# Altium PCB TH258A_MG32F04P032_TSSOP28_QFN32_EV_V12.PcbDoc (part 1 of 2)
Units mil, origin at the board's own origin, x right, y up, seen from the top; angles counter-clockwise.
Board outline 4094.49 x 2637.8 mil, 2 copper layers (Top Layer, Bottom Layer); 115 components, 96 nets, 518 pads, 260 vias.
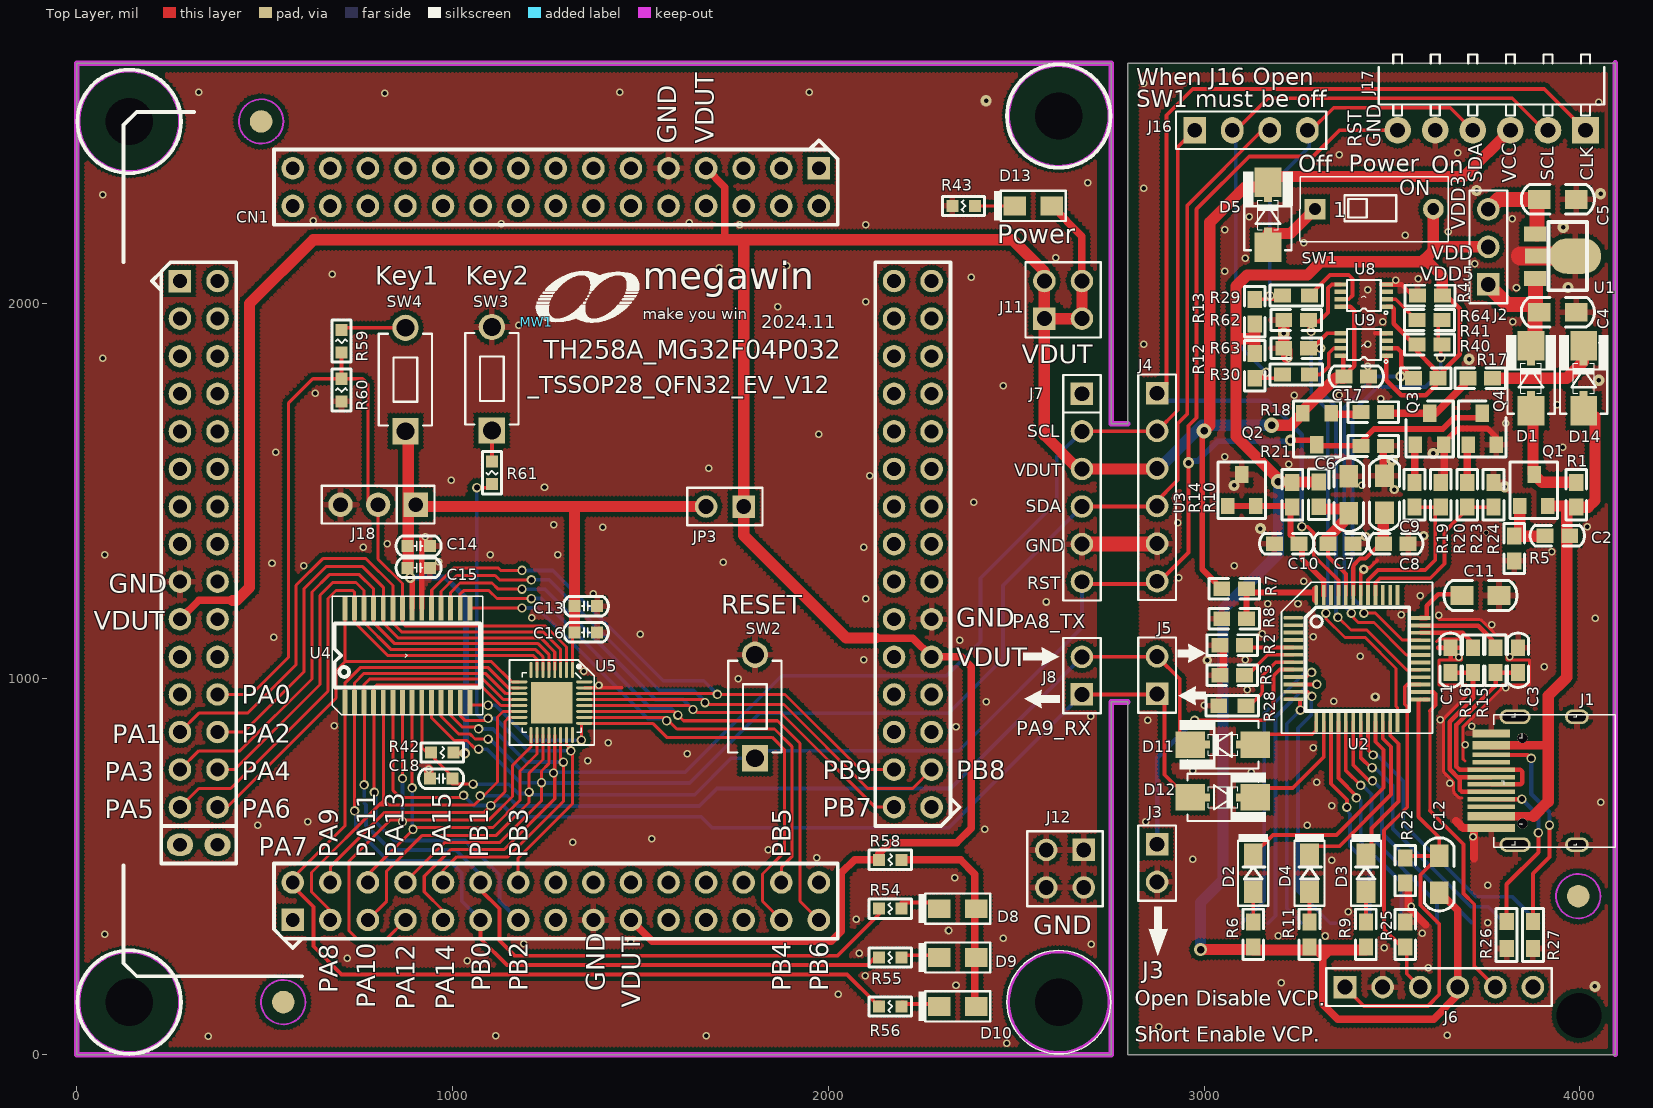
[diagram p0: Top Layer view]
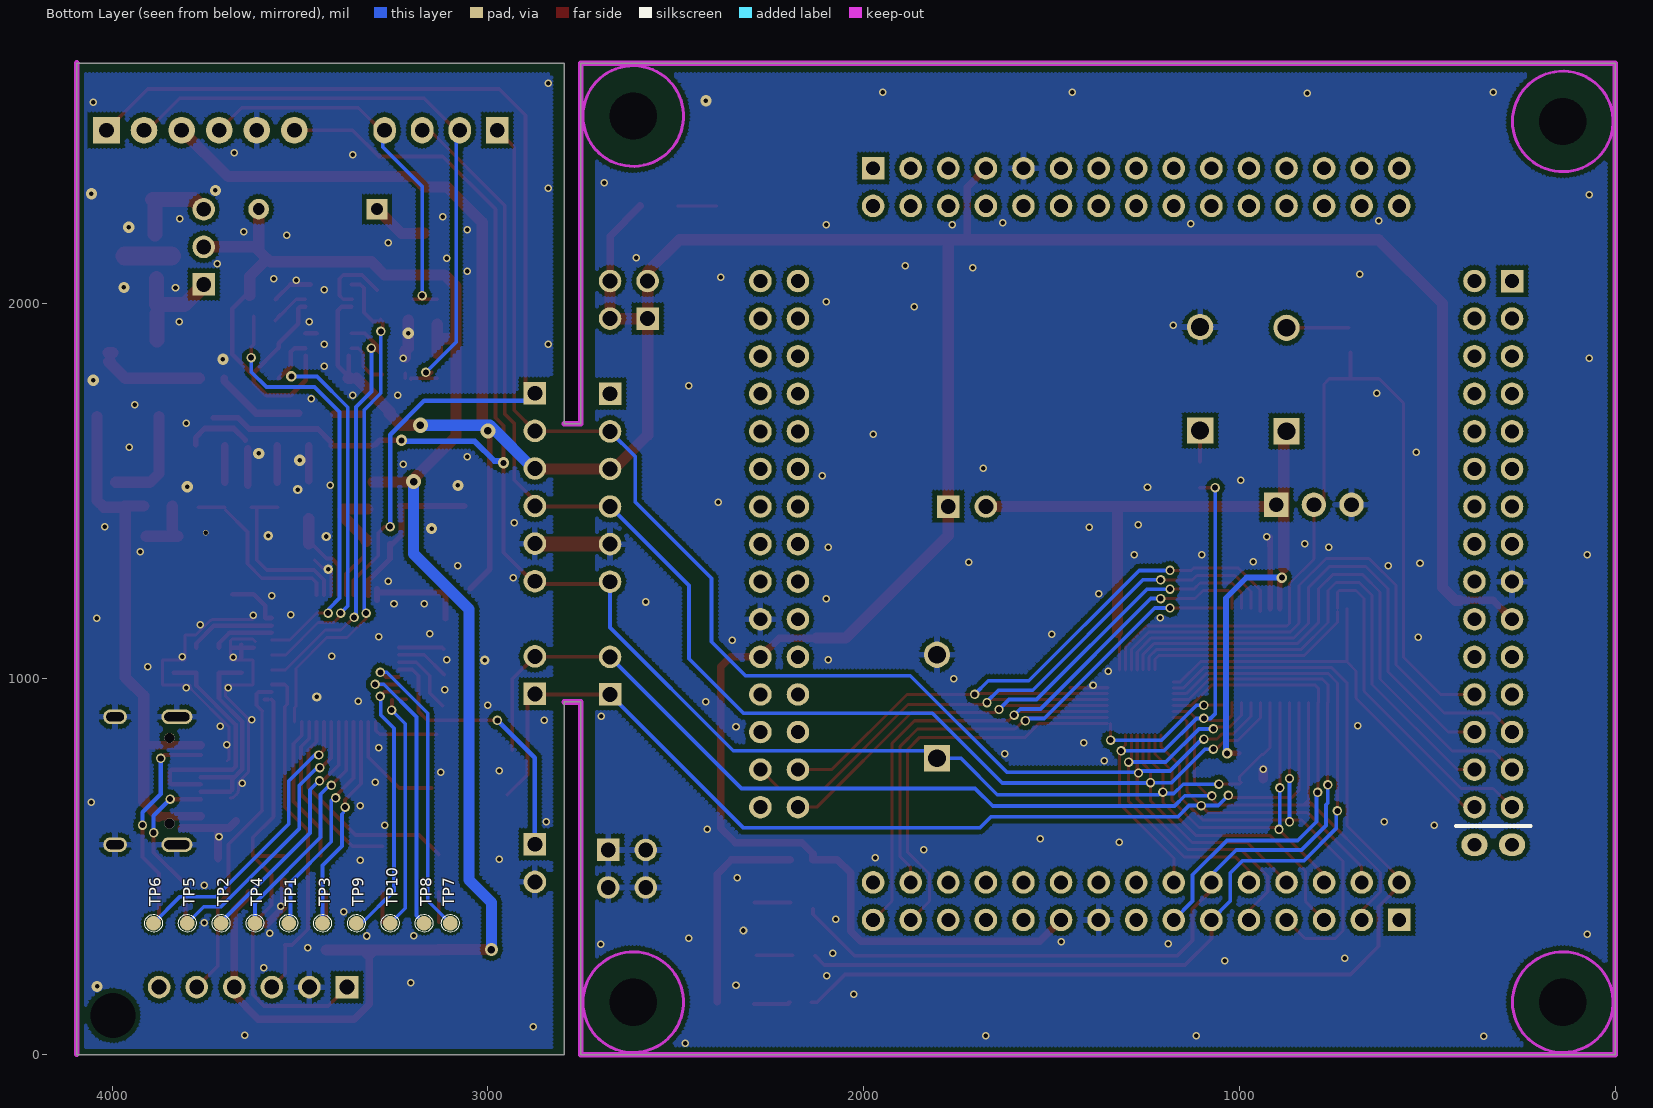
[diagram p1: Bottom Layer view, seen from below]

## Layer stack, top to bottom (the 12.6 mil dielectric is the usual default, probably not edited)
Top Layer: signal copper 1.4
Dielectric: dielectric 12.6, FR-4, Dk 4.8
Bottom Layer: signal copper 1.4

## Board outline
0,0 0,2637.8 2753.39,2637.8 2753.39,1678.74 2796.69,1678.74 2796.69,2637.8 4094.49,2637.8 4094.49,0 2796.69,0 2796.69,938.74 2753.39,938.74 2753.39,0

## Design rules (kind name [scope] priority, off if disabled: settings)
Clearance 12 [All] p1 off: gap=12
Clearance 7 [All] p2 off: gap=7
Clearance 6 [All] p3: gap=6
HoleSize 500-HoleSize [All] p1: absolutevalues=TRUE maxlimit=1500 minlimit=1 maxpercent=80.000 minpercent=20.000
PolygonConnect VIA [ISVIA] p1: connectstyle=Direct reliefconductorwidth=10 reliefentries=4 polygonreliefangle="90 Angle"
PolygonConnect "15 PolygonConnect" [All] p2: connectstyle=Relief reliefconductorwidth=15 reliefentries=4 polygonreliefangle="90 Angle"
RoomDefinition "3_MG32F04P032_QFN32 " [InComponentClass('3_MG32F04P032_QFN32 ')] p1: confinementstyle=ConfineIn formatcopy=TRUE lockcomponents=FALSE outline -14,-77 4129,-77 4129,2722 -14,2722
RoomDefinition 2_MG32F04P032_TSSOP28_V11 [InComponentClass('2_MG32F04P032_TSSOP28_V11')] p2: confinementstyle=ConfineIn formatcopy=TRUE lockcomponents=FALSE outline -39,-59 4148,-59 4148,2700 -39,2700
RoomDefinition 1_MLink_V14 [InComponentClass('1_MLink_V14')] p3: confinementstyle=ConfineIn formatcopy=TRUE lockcomponents=FALSE outline -63,-44 4163,-44 4163,2685 -63,2685
RoutingVias [All] p1: holewidth=16 width=25 viastyle="Through Hole" minholewidth=12 minwidth=25 maxholewidth=28 maxwidth=50
ShortCircuit [All] p1 off: allowed=FALSE
SilkscreenOverComponentPads [All] p1: minsilkscreentomaskgap=10
SolderMaskExpansion [All] p1: expansion=4
UnRoutedNet [All] p1 off:
Width [All] p1: maxlimit=100 minlimit=6 preferedwidth=8
24 further rules are at their usual default settings.

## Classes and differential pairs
component class 2_MG32F04P032_TSSOP28_V11: C14 C15 C18 CN1 D8 D9 D10 D13 J7 J8 J11 J12 J18 JP3 R42 R43 R54 R55 R56 R58 R59 R60 R61 SW2 SW3 SW4 U4
component class 1_MLink_V14: C1 C2 C3 C4 C5 C6 C7 C8 C9 C10 C11 C12 C17 D1 D2 D3 D4 D5 D11 D12 D14 J1 J2 J3 J4 J5 J6 J16 J17 MW1 Q1 Q2 Q3 Q4 R1 R2 R3 R4 R5 R6 R7 R8 R9 R10 R11 R12 R13 R14 R15 R16 R17 R18 R19 R20 R21 R22 R23 R24 R25 R26 R27 R28 R29 R30 R40 R41 R62 R63 R64 SW1 TP1 TP2 TP3 TP4 TP5 TP6 TP7 TP8 TP9 TP10 U1 U2 U3 U8 U9
component class "3_MG32F04P032_QFN32 ": C13 C16 U5

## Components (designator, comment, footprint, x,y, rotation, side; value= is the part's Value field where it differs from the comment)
C1 "15pF" 0603C 3655.59,1050 r270 top
C2 "0.1uF" 0603C 3940,1381.26 r0 top
C3 "15pF" 0603C 3835.59,1050 r270 top
C4 "4.7uF" 0805C 3941.38,1975.94 r0 top
C5 "4.7uF" 0805C 3941.38,2275.94 r0 top
C6 "4.7uF" 0805C 3385,1490 r90 top
C7 "0.1uF" 0603C 3363,1360 r0 top
C8 "0.1uF" 0603C 3510,1360 r0 top
C9 "4.7uF" 0805C 3480,1491.26 r90 top
C10 "0.1uF" 0603C 3220,1360 r0 top
C11 "4.7uF" 0805C 3735.59,1221.9 r0 top
C12 "4.7uF" 0805C 3625.59,480 r90 top
C13 "10uF" C-0603 1355.04,1193.74 r0 top
C14 "10uF" C-0603 910,1353.74 r180 top
C15 "0.1uF" C-0603 910,1295.74 r180 top
C16 "0.1uF" C-0603 1355.04,1123.74 r0 top
C17 "0.1uF" 0603C 3405,1805 r180 top
C18 "4.7uF" C-0603 970,735 r0 top
CN1 "QFP122-CKT" QFP122-P2.54-CKT 1275.04,1358.74 r0 top locked
D1 "1N5817" DIODE_SMA_SOD323 3870,1800 r90 top
D2 "Yellow" 0805D 3130.59,483.26 r90 top
D3 "Green" 0805D 3430.59,483.26 r90 top
D4 "Red" 0805D 3280.59,483.26 r90 top
D5 "1N5817" DIODE_SMA_SOD323 3170,2235 r90 top
D8 "Red" 0805D 2344.25,388.74 r180 top
D9 "Yellow" 0805D 2344.25,258.74 r180 top
D10 "Green" 0805D 2344.25,128.74 r180 top
D11 "1N5817" DIODE_SMA_SOD323 3050.04,825 r180 top
D12 "1N5817" DIODE_SMA_SOD323 3050.04,685 r0 top
D13 "Yellow" 0805D 2545.04,2258.74 r180 top
D14 "1N5817" DIODE_SMA_SOD323 4010,1800 r90 top
J1 "CJ-USB3-C16P" USB_CF_16_SMD 3799.28,729.12 r90 top
J2 "2&3 (0 ohm)" PS3P254#1 3756.42,2049.69 r90 top
J3 "VCP Option" PS2P254 2875.04,560 r270 top
J4 "OnBoard ICP/SWD Connector" PS6P254 2875.04,1760 r270 top
J5 "NC" PS2P254 2875.04,960 r90 top
J6 "CON6" PS6P254 3375.04,180 r0 top
J7 "CON6" PS6P254 2675.04,1758.74 r270 top locked
J8 "NC" PS2P254 2675.04,958.74 r90 top
J11 "CONN SOCKET 2x2/SM" PS2X2P254 2575.04,1958.74 r0 top
J12 "CONN SOCKET 2x2/SM" PS2X2P254 2680,545 r180 top
J16 "When J16 Open, SW1 must be off." PS4P254 2975.04,2460 r0 top
J17 "Off Board ICP/SWD Connector" PS6P254_90 4015.04,2460 r180 top locked
J18 "2&3 (0 ohm)" PS3P254#2 902.2,1463.74 r180 top
JP3 "JUMPER" PS2P254 1775.04,1458.74 r180 top
MW1 "MW-A4" MEGAWIN_3.4_1 1225.04,1948.74 r0 top
Q1 "IRLML6402" SOT23 3877.54,1501.97 r0 top
Q2 "2N3906" SOT23 3300.5,1665 r180 top
Q3 "3904" SOT23_132 3600.04,1665 r0 top
Q4 "3904" SOT23_132 3740.04,1665 r0 top
R1 "NC" 0603R#1 3990.04,1490 r270 top
R2 "NC" 0603R#1 3075.04,1090 r0 top
R3 "NC" 0603R#1 3075.04,1010 r0 top
R4 "3.3K" 0603R#1 3601,2020 r0 top
R5 "1M" 0603R#1 3825.04,1347 r270 top
R6 "1K" 0603R#1 3130.59,320.26 r270 top
R7 "30K" 0603R#1 3080,1240 r180 top
R8 "10K" 0603R#1 3080,1160 r0 top
R9 "1K" 0603R#1 3430.59,320.26 r270 top
R10 "10" 0603R#1 3305,1491.26 r90 top
R11 "1K" 0603R#1 3280.59,320.26 r270 top
R12 "1.5K" 0603R#1 3135,1833 r90 top
R13 "1.5K" 0603R#1 3135,1977 r270 top
R14 "1K" 0603R#1 3235,1490 r270 top
R15 "30" 0603R#1 3775.59,1050 r90 top
R16 "30" 0603R#1 3715.59,1050 r90 top
R17 "4.7K" 0603R#1 3735,1800 r0 top
R18 "1K" 0603R#1 3450.04,1710 r0 top
R19 "4.7K" 0603R#1 3560.04,1490 r270 top
R20 "10K" 0603R#1 3630.04,1490 r270 top
R21 "1M" 0603R#1 3450.04,1620 r180 top
R22 "47K" 0603R#1 3535.59,490 r270 top
R23 "4.7K" 0603R#1 3700.04,1490 r270 top
R24 "10K" 0603R#1 3770.04,1490 r270 top
R25 "47K" 0603R#1 3535.59,320 r270 top
R26 "5.1K" 0603R#2 3805.04,318.74 r270 top
R27 "5.1K" 0603R#2 3875.04,318.74 r90 top
R28 "0" 0603R#2 3075.04,928.74 r180 top
R29 "100" 0603R#2 3245,2020 r0 top
R30 "100" 0603R#2 3245,1810 r0 top
R40 "NC" 0603R#1 3590,1800 r180 top
R41 "1.5K" 0603R#1 3600,1890 r0 top
R42 "47K" R-0603 972.9,804.1 r180 top
R43 "1K" R-0603 2360.04,2258.74 r0 top
R54 "470" R-0603 2165.04,388.74 r0 top
R55 "470" R-0603 2165.04,258.74 r0 top
R56 "470" R-0603 2165.04,128.74 r0 top
R58 "0" R-0603 2165.04,518.74 r180 top
R59 "1K" R-0603 705.04,1898.74 r270 top
R60 "1M" R-0603 705.04,1768.74 r270 top
R61 "1K" R-0603 1105.04,1548.74 r90 top
R62 "47k" 0603R#3 3245,1955 r0 top
R63 "47k" 0603R#3 3245,1880 r0 top
R64 "100" 0603R#3 3600,1955 r180 top
SW1 "SW KEY-SPST" DIP2_SW 3295.04,2250 r0 top
SW2 "SW TACT-SPST" SW_T_2P 1805.04,926.54 r90 top
SW3 "Key2" SW_T_2P 1105.04,1798.74 r90 top
SW4 "Key1" SW_T_2P 875.04,1796.54 r90 top
TP1 "T POINT A" PIN1_1H0 3530.04,350 r90 bottom
TP2 "T POINT A" PIN1_1H0 3710.04,350 r90 bottom
TP3 "T POINT A" PIN1_1H0 3440.04,350 r180 bottom
TP4 "T POINT A" PIN1_1H0 3620.04,350 r180 bottom
TP5 "T POINT A" PIN1_1H0 3800.04,350 r180 bottom
TP6 "T POINT A" PIN1_1H0 3890.04,350 r180 bottom
TP7 "T POINT A" PIN1_1H0 3100.04,350 r180 bottom
TP8 "T POINT A" PIN1_1H0 3170.04,350 r180 bottom
TP9 "T POINT A" PIN1_1H0 3350.04,350 r180 bottom
TP10 "T POINT A" PIN1_1H0 3260.04,350 r90 bottom
U1 "AIC1734-33(SOT-89)" SOT89 3881.38,2125 r270 top
U2 "MG84FG516_LQFP48" LQFP48_7X7_050 3406.51,1054.39 r270 top locked
U3 "TL431A" SOT23 3100,1501.97 r0 top
U4 "MG32F04P032_TSSOP28_170P0.65" TSSOP28_170P065 880.04,1062.5 r0 top locked
U5 "MG32F04P032_QFN32_4X4P0.4" QFN32_4X4P040 1264.41,937.13 r270 top locked
U8 "SN74LVC2T45 (MSOP8_90P0.5)" MSOP8_90P0.5 3425,2020 r90 top
U9 "SN74LVC2T45 (MSOP8_90P0.5)" MSOP8_90P0.5 3425,1890 r90 top

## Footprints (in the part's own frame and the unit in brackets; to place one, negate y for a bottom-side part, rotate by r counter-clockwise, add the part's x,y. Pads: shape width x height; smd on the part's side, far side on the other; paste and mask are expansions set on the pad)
0603C [mil]
  rect 45x38 smd: 1(33,0) 2(-33,0)
  silkscreen extent -72,-28 72,28
0603R#1 [mil]
  rect 45x38 smd: 1(33,0) 2(-33,0)
  silkscreen extent -67,-28 67,28
0603R#2 [mil]
  rect 45x38 smd: 1(-36,0) 2(36,0)
  silkscreen extent -70,-28 70,28
0603R#3 [mil]
  rect 45x38 smd: 1(-33,0) 2(33,0)
  silkscreen extent -67,-28 67,28
0805C [mil]
  rect 60x50 smd: 1(-49.21,0) 2(49.21,0)
  silkscreen extent -97,-39 97,39
0805D [mil]
  rect 60x50 smd: 1(-49.21,0) 2(49.21,0)
  silkscreen extent -87,-40 104,40
C-0603 [mil]
  rect 32x32 smd: 1(-30,0) 2(30,0)
  silkscreen extent -60,-26 60,26
DIODE_SMA_SOD323 [mm]
  rect 2x1.8 smd: 1(-2.2,0) 2(2.2,0)
  rect 0.95x0.54 smd: 1(-1.35,0) 2(1.35,0)
  silkscreen extent -2.4,-1.68 2.92,1.68
DIP2_SW [mm]
  rect 1.4x1.4 hole 0.8: 1(0,0)
  round 1.4 hole 0.8: 2(8,0)
  silkscreen extent -1.02,-2.2 9.02,2.2
LQFP48_7X7_050 [mm]
  oval 0.254x1.35 smd: 1(-2.75,-4.292)
  rect 0.254x1.35 smd: 2(-2.25,-4.292) 3(-1.75,-4.292) 4(-1.25,-4.292) 5(-0.75,-4.292) 6(-0.25,-4.292) 7(0.25,-4.292) 8(0.75,-4.292) 9(1.25,-4.292) 10(1.75,-4.292) 11(2.25,-4.292) 12(2.75,-4.292) 25(2.763,4.292) 26(2.263,4.292) 27(1.763,4.292) 28(1.263,4.292) 29(0.763,4.292) 30(0.263,4.292) 31(-0.237,4.292) 32(-0.737,4.292) 33(-1.237,4.292) 34(-1.737,4.292) 35(-2.237,4.292) 36(-2.737,4.292)
  rect 1.35x0.254 smd: 13(4.286,-2.744) 14(4.286,-2.244) 15(4.286,-1.744) 16(4.286,-1.244) 17(4.286,-0.744) 18(4.286,-0.244) 19(4.286,0.256) 20(4.286,0.756) 21(4.286,1.256) 22(4.286,1.756) 23(4.286,2.256) 24(4.286,2.756) 37(-4.286,2.756) 38(-4.286,2.256) 39(-4.286,1.756) 40(-4.286,1.256) 41(-4.286,0.756) 42(-4.286,0.256) 43(-4.286,-0.244) 44(-4.286,-0.744) 45(-4.286,-1.244) 46(-4.286,-1.744) 47(-4.286,-2.244)
  oval 1.35x0.254 smd: 48(-4.286,-2.744)
  silkscreen extent -5.15,-5.09 5.05,5.11
MEGAWIN_3.4_1 [mil]
  silkscreen extent -2,0 272,135
MSOP8_90P0.5 [mm]
  rect 0.3x0.85 smd: 1(-0.75,-1.55) 2(-0.25,-1.55) 3(0.25,-1.55) 4(0.75,-1.55) 5(0.75,1.55) 6(0.25,1.55) 7(-0.25,1.55) 8(-0.75,1.55)
  silkscreen extent -1.26,-1.61 1.05,1.14
PIN1_1H0 [mm]
  round 1 smd: 1(0,0)
  silkscreen extent -0.6,-0.6 0.6,0.6
PS2P254 [mil]
  rect 60x60 hole 39.37: 1(0,0)
  round 60 hole 39.37: 2(100,0)
  silkscreen extent -50,-50 150,50
PS2X2P254 [mil]
  rect 60x60 hole 39.37: 1(0,0)
  round 60 hole 39.37: 2(0,100) 3(100,0) 4(100,100)
  silkscreen extent -50,-50 150,150
PS3P254#1 [mil]
  rect 60x60 hole 39.37: 1(0,0)
  round 60 hole 39.37: 2(100,0) 3(200,0)
  silkscreen extent -50,-50 250,50
PS3P254#2 [mil]
  rect 65x65 hole 39.37: 1(0,0)
  round 65 hole 39.37: 2(100,0) 3(200,0)
  silkscreen extent -50,-50 250,50
PS4P254 [mil]
  rect 60x70 hole 39.37: 1(0,0)
  oval 60x70 hole 39.37: 2(100,0) 3(200,0) 4(300,0)
  silkscreen extent -50,-50 350,50
PS6P254 [mil]
  rect 60x60 hole 39.37: 1(0,0)
  round 60 hole 39.37: 2(100,0) 3(200,0) 4(300,0) 5(400,0) 6(500,0)
  silkscreen extent -50,-50 550,50
PS6P254_90 [mm]
  rect 1.8x1.8 hole 1: 1(0,0)
  round 1.8 hole 1: 2(2.54,0) 3(5.08,0) 4(7.62,0) 5(10.16,0) 6(12.7,0)
  silkscreen extent -1.27,-5.11 13.97,-1
QFN32_4X4P040 [mm]
  oval 1.1x0.2 smd: 1(-2.2,1.4) 2(-2.2,1) 3(-2.2,0.6) 4(-2.2,0.2) 5(-2.2,-0.2) 6(-2.2,-0.6) 7(-2.2,-1) 8(-2.2,-1.4) 17(2.2,-1.4) 18(2.2,-1) 19(2.2,-0.6) 20(2.2,-0.2) 21(2.2,0.2) 22(2.2,0.6) 23(2.2,1) 24(2.2,1.4)
  oval 0.2x1.1 smd: 9(-1.4,-2.2) 10(-1,-2.2) 11(-0.6,-2.2) 12(-0.2,-2.2) 13(0.2,-2.2) 14(0.6,-2.2) 15(1,-2.2) 16(1.4,-2.2) 25(1.4,2.2) 26(1,2.2) 27(0.6,2.2) 28(0.2,2.2) 29(-0.2,2.2) 30(-0.6,2.2) 31(-1,2.2) 32(-1.4,2.2)
  rect 2.8x2.8 smd: 33(0,0)
  silkscreen extent -2.87,-2.87 2.87,2.87
QFP122-P2.54-CKT [mil]
  rect 60x60 hole 37: 1(-700,-1000) 61(700,1000) 91(-1000,700)
  round 60 hole 37: 2(-700,-900) 3(-600,-1000) 4(-600,-900) 5(-500,-1000) 6(-500,-900) 7(-400,-1000) 8(-400,-900) 9(-300,-1000) 10(-300,-900) 11(-200,-1000) 12(-200,-900) 13(-100,-1000) 14(-100,-900) 15(0,-1000) 16(0,-900) 17(100,-1000) 18(100,-900) 19(200,-1000) 20(200,-900) 21(300,-1000) 22(300,-900) 23(400,-1000) 24(400,-900) 25(500,-1000) 26(500,-900) 27(600,-1000) 28(600,-900) 29(700,-1000) 30(700,-900) 31(1000,-700) 32(900,-700) 33(1000,-600) 34(900,-600) 35(1000,-500) 36(900,-500) 37(1000,-400) 38(900,-400) 39(1000,-300) 40(900,-300) 41(1000,-200) 42(900,-200) 43(1000,-100) 44(900,-100) 45(1000,0) 46(900,0) 47(1000,100) 48(900,100) 49(1000,200) 50(900,200) 51(1000,300) 52(900,300) 53(1000,400) 54(900,400) 55(1000,500) 56(900,500) 57(1000,600) 58(900,600) 59(1000,700) 60(900,700) 62(700,900) 63(600,1000) 64(600,900) 65(500,1000) 66(500,900) 67(400,1000) 68(400,900) 69(300,1000) 70(300,900) 71(200,1000) 72(200,900) 73(100,1000) 74(100,900) 75(0,1000) 76(0,900) 77(-100,1000) 78(-100,900) 79(-200,1000) 80(-200,900) 81(-300,1000) 82(-300,900) 83(-400,1000) 84(-400,900) 85(-500,1000) 86(-500,900) 87(-600,1000) 88(-600,900) 89(-700,1000) 90(-700,900) 92(-900,700) 93(-1000,600) 94(-900,600) 95(-1000,500) 96(-900,500) 97(-1000,400) 98(-900,400) 99(-1000,300) 100(-900,300) 101(-1000,200) 102(-900,200) 103(-1000,100) 104(-900,100) 105(-1000,0) 106(-900,0) 107(-1000,-100) 108(-900,-100) 109(-1000,-200) 110(-900,-200) 111(-1000,-300) 112(-900,-300) 113(-1000,-400) 114(-900,-400) 115(-1000,-500) 116(-900,-500) 117(-1000,-600) 118(-900,-600) 119(-1000,-700) 120(-900,-700)
  oval 70x60 hole 37: 121(-1000,-800) 122(-900,-800)
  silkscreen extent -1150,-1150 1075,1150
R-0603 [mil]
  rect 32x32 smd: 1(-30,0) 2(30,0)
  silkscreen extent -56,-26 56,26
SOT23 [mil]
  rect 36x43.31 smd: 1(-37.5,-41.97) 2(37.5,-41.97)
  rect 36x46.06 smd: 3(0.5,41.97)
  silkscreen extent -63,-74 63,75
SOT23_132 [mil]
  rect 36x43.31 smd: 1(-37.5,-41.97) 3(37.5,-41.97)
  rect 36x46.06 smd: 2(0.5,41.97)
  silkscreen extent -63,-74 63,75
SOT89 [mm]
  rect 1.016x1.5 smd: 1(-1.5,0) 3(1.5,0)
  oval 2.4x3.5 smd: 2(0,2.7)
  rect 1.016x2.6 smd: 2(0,0.6)
  silkscreen extent -2.3,0.9 2.3,3.5
SW_T_2P [mil]
  rect 70x70 hole 47.24: 1(-137.79,0)
  round 70 hole 47.24: 2(137.79,0)
  silkscreen extent -122,-71 122,71
TSSOP28_170P065 [mil]
  rect 13x65 smd: 1(-166.34,-125) 2(-140.75,-125) 3(-115.16,-125) 4(-89.57,-125) 5(-63.98,-125) 6(-38.39,-125) 7(-12.8,-125) 8(12.8,-125) 9(38.39,-125) 10(63.98,-125) 11(89.57,-125) 12(115.16,-125) 13(140.75,-125) 14(166.34,-125) 15(166.34,125) 16(140.75,125) 17(115.16,125) 18(89.57,125) 19(63.98,125) 20(38.39,125) 21(12.8,125) 22(-12.8,125) 23(-38.39,125) 24(-63.98,125) 25(-89.57,125) 26(-115.16,125) 27(-140.75,125) 28(-166.34,125)
  silkscreen extent -200,-158 201,158
USB_CF_16_SMD [mm]
  rect 0.55x3.2 smd: A1(-3.2,0.9) A4(-2.4,0.9)
  rect 0.3x3.2 smd: A5(-1.25,0.9) A6(-0.25,0.9) A7(0.25,0.9) B6(0.75,0.9) B7(-0.75,0.9) B8(-1.75,0.9)
  rect 0.3x2.54 smd: A8(1.25,0.9) B5(1.75,0.9)
  rect 0.55x2.54 smd: A9(2.4,0.9) A12(3.2,0.9)
  oval 1x2.1 hole 0.6 slot 1.7 at 90 deg: M1(-4.32,-0.718) M2(4.32,-0.718)
  oval 1x1.6 hole 0.6 slot 1.2 at 90 deg: M3(4.32,-4.898) M4(-4.32,-4.898)
  round 0.7 hole 0.7 unplated: M5(-2.89,-1.218) M6(2.89,-1.218)
  silkscreen extent -4.48,-7.5 4.55,0.74

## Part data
C1 C3 C7 C12 C13 C14 C15 C16 C18: library part "CAP NP_Dup1"
C2 C8 C10 C17: library part "CAP NP"
C4 C5: library part "C NP"
C6 C9 C11: library part CAP
D1 D5 D11 D12 D14: library part "DIODE SCHOTTKY"
D2 D3 D4: library part Led0_0
D8 D9 D10 D13: library part LED
J1: "TPYE-C-9"
J2 J18: library part CON3
J3 J5 J8: library part CON2
J4 J17: library part CON6
J7: library part CON6_Dup1
J16: library part CON4
MW1: library part MW_A4_2
Q1: library part "MOSFET P GSD"
Q2: library part 2N3906_0
Q3 Q4: library part "NPN BCE"
R1 R2 R3 R4 R28 R43 R54 R55 R56 R58: library part R_Dup4
R5 R6 R7 R8 R9 R11 R12 R13 R17 R18 R19 R22 R23 R25 R26 R27 R29 R30: library part R_Dup2
R10 R14 R15 R16: library part R_Dup5
R20 R21 R24: library part R_Dup1
R40 R41 R42 R59 R60 R61 R62 R63: library part R_Dup3
R64: library part R
SW3 SW4: library part "SW TACT-SPST"
U1: library part AIC1722-33
U3: library part TL431/CYL
U4: library part MDF101A/TSSOP28
U5: library part MG32F005_QFN32
U8 U9: library part SN74LVC2T45

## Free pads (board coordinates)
  round 120 hole 125.98 unplated: 0(140,140) 0(140,2483.43) 0(2613.39,140) 0(2613.39,2497.8)
  round 60 smd mask+39.37: 0(491,2483.43) 0(550,140) 0(3995.59,421.9)
  round 100 hole 120 unplated: 0(3997.8,104.65)

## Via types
v1: diameter 20, hole 12, Top Layer to Bottom Layer, tented both sides, 172 vias
v2: diameter 25, hole 16, Top Layer to Bottom Layer, tented both sides, 58 vias
v3: diameter 30, hole 12, Top Layer to Bottom Layer, tented both sides, 14 vias
v4: diameter 25, hole 12, Top Layer to Bottom Layer, tented both sides, 6 vias
v5: diameter 40, hole 20, Top Layer to Bottom Layer, tented both sides, 3 vias
v6: diameter 28, hole 16, Top Layer to Bottom Layer, tented both sides, 3 vias
v7: diameter 30, hole 16, Top Layer to Bottom Layer, tented both sides, 2 vias
v8: diameter 15, hole 12, Top Layer to Bottom Layer, tented both sides, 1 vias
v9: diameter 35, hole 20, Top Layer to Bottom Layer, tented both sides, 1 vias

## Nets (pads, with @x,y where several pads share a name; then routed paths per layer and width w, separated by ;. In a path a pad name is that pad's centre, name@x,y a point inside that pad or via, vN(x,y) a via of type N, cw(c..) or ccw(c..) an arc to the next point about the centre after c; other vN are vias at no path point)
2.495V: C10.1 R14.1 U2.47 U3.1 U3.2 | length 442.3
  Top Layer w15: U3.1@3062.5,1460 U3.2@3137.5,1460 R14.1@3235,1460 ; R14.1@3230,1452 3230,1383 C10.1@3253,1360 3260.59,1360 3260.59,1319.45 3318.18,1261.86 U2.47@3318.18,1223.13
516P24: TP7.1 U2.9 | length 807.9
  Top Layer w10: U2.9@3237.52,1005.18 3271.48,1005.18 v2@3285.04,1018.74
  Bottom Layer w10: TP7.1@3100.04,350 3160.04,410 3160.04,908.74 3269.04,1017.74 v2(3286.04,1017.74)
516P25: TP8.1 U2.10 | length 765.6
  Top Layer w10: U2.10@3237.52,985.49 v2@3300.04,985.49
  Bottom Layer w10: TP8.1@3170.04,350 3190.04,370 3190.04,898.74 3277.04,985.74 v2(3300.04,985.74)
516P26: TP9.1 U2.11 | length 719.6
  Top Layer w10: U2.11@3237.52,965.81 3275.04,965.81 v2@3285.04,955.81
  Bottom Layer w10: v2@3285.04,953.74 3285.04,903.74 3250.04,868.74 3250.04,435.95 3335.99,350 TP9.1@3350.04,350
  other v2: 3287.04,953.74
516P27: TP10.1 U2.12 | length 651.8
  Top Layer w10: U2.12@3217.15,946.12 U2.12@3237.52,946.12 ; v2@3255.04,911.51 3255.04,916.74 U2.12@3255.04,944.74
  Bottom Layer w10: v2(3256.04,916.74) 3220.04,880.74 3220.04,390 TP10.1@3260.04,350
516P32: TP3.1 U2.15 | length 550.9
  Top Layer w10: U2.15@3337.86,885.65 3337.86,720.92 3380.04,678.74 v2@3380.04,668.74
  Bottom Layer w10: 3385.04,643.74 3388.62,640.16 3388.62,555.16 3440.04,503.74 TP3.1@3440.04,350
  other v2: 3380.04,658.74
516P33: TP1.1 U2.16 | length 664
  Top Layer w10: U2.16@3357.55,885.65 3357.55,736.23 v2@3407.54,686.24 ; v2@3409.54,688.24 v2@3412.04,685.74
  Bottom Layer w10: v2@3405.04,688.74 3407.54,686.24 3416.9,676.88 3416.9,566.88 ; 3416.9,618.74 3416.9,566.88 ; TP1.1@3525.04,350 3525.04,458.74 3416.9,566.88
  other v2: 3405.04,683.74
516P34: TP4.1 U2.17 | length 635.3
  Top Layer w10: U2.17@3377.23,885.65 3377.23,756.55 v2(3416.72,717.06)
  Bottom Layer w10: v2@3420.64,717.8 3445.19,693.26 3445.19,578.59 3620.04,403.74 TP4.1@3620.04,350
516P35: TP2.1 U2.18 | length 668.2
  Top Layer w10: U2.18@3396.92,885.65 3396.92,770.86 3443.54,724.24 v2@3445.04,722.74
  Bottom Layer w10: v2@3450.04,728.74 3473.47,705.31 3473.47,590.31 TP2.1@3711.91,351.87
  other v2: 3448.04,728.74
516P36: TP5.1 U2.19 | length 736.6
  Top Layer w10: U2.19@3416.6,885.65 3416.6,791.18 v2@3445.54,762.24
  Bottom Layer w10: v2(3447.04,763.74) 3455.04,763.74 3501.76,717.02 3501.76,602.02 3710.04,393.74 3756.3,393.74 TP5.1@3800.04,350 TP5.1@3790.59,350
516P37: TP6.1 U2.20 | length 795.9
  Top Layer w10: U2.20@3436.29,885.65 3436.29,811.49 v2(3450.04,797.74)
  Bottom Layer w10: v2(3450.04,797.74) 3461.04,797.74 3530.04,728.74 3530.04,613.74 3723.04,420.74 3819.3,420.74 TP6.1@3890.04,350 TP6.1@3880.59,350
CHIP_VDD: C13.1 C14.2 C15.2 C16.1 J18.1 JP3.2 R42.1 SW4.1 U4.21 U5.1 | length 2309.8
  Top Layer w9: U5.1@1319.53,1023.74 C16.1@1319.53,1123.74
  Top Layer w15: U4.21@892.83,1187.5 v6@892.83,1269.74 ; R42.1@1003,802 v6@1028.59,802
  Top Layer w30: C15.2@882.2,1295.74 C14.2@882.2,1353.74 ; C14.2@882.2,1365.74 C14.2@882.2,1353.74 ; SW4.1@882.2,1658.74 882.2,1463.74 J18.1@882.2,1443.74 ; SW4.1@888,1658.74 SW4.1@888,1660 ; J18.1@902.2,1463.74 J18.1@897.2,1458.74 ; C16.1@1325.04,1123.74 C13.1@1325.04,1193.74 1325.04,1458.74 ; JP3.2@1675.04,1458.74 1325.04,1458.74 ; C14.2@882.2,1353.74 J18.1@882.2,1443.74 ; J18.1@882.2,1443.74 J18.1@897.2,1458.74 ; J18.1@897.2,1458.74 902.2,1458.74 1325.04,1458.74
  Bottom Layer w15: v6(887.2,1269.74) 981.42,1269.74 1036,1215.16 v6@1036,802
  other v6: 1033,802
D+: C3.1 J1.A6 J1.B6 R15.2 | length 648.6
  Top Layer w12: J1.A6@3763.84,719.27 3842.37,719.27 3847.09,724 3847.09,753 3841.45,758.64 J1.B6@3763.84,758.64 3679.95,758.64 3671.59,767 3671.59,878.54 3775.59,982.54 R15.2@3775.59,1017 C3.1@3835.59,1017
D-: C1.1 J1.A7 J1.B7 R16.2 | length 590.1
  Top Layer w12: C1.1@3655.59,1017 R16.2@3715.59,1017 3715.59,948 3653.59,886 3653.59,759.54 3679.75,733.39 ; 3675.59,738.96 3685.99,738.96 ; 3680.59,734.23 3680.59,705.23 3686.23,699.59 J1.B7@3763.84,699.59 ; 3680.94,733.9 3685.99,738.96 ; J1.A7@3763.84,738.96 3685.99,738.96
DET_VDUT: R7.2 R8.1 U2.48 | length 292.1
  Top Layer w15: R8.1@3113,1160 R7.2@3113,1240 3123,1230 3290.98,1230 ; U2.48@3295.04,1210 3295.04,1223.13 U2.48@3295.04,1240
DUT_CLK: J4.1 J17.1 U2.45 | length 2846.5
  Top Layer w10: J4.1@2875.04,1760 2900.04,1785 2900.04,2500.04 2970,2570 3905.04,2570 J17.1@4015.04,2460 ; v2(3260,1405) 3275,1405 3292,1388 3292,1327.92 3357.55,1262.37 U2.45@3357.55,1223.13
  Bottom Layer w12: J4.1@2875.04,1760 2880.04,1760 2900.04,1740 3170,1740 3260,1650 v2(3260,1405)
DUT_RST: C18.2 CN1.5 J4.6 J7.6 J17.6 Q2.3 Q4.2 R21.1 R42.2 SW2.1 U4.9 U5.19 | length 5742.6
  Top Layer w8: CN1.5@775.04,358.74 825.04,408.74 825.04,488.74 920.04,583.74 1116.74,583.74 1204.04,671.04 v2(1204.04,698.74) 1204.04,749.04 1240.79,785.79 U5.19@1240.79,850.51 ; U4.9@918.43,937.5 918.43,817.57 937.4,798.6 941.4,798.6 1000,740 C18.2@1000,735 C18.2@1000,730 ; C18.2@995,725 1000,720 v2(1055,720)
  Top Layer w10: J7.6@2676.04,1252.74 2875.04,1252.74 2878.67,1256.37 2958.79,1336.49 v7(2958.79,1575) 2958.79,1673.79 2980.04,1695.04 2980.04,2250.04 3120,2390 3290,2390 3360,2460 J17.6@3515.04,2460
  Top Layer w15: v7(3230,1635) 3288.03,1635 Q2.3@3300,1623.03 ; Q2.3@3308.03,1620 R21.1@3417.04,1620 3417.04,1629.56 3452.48,1665 3635,1665 3665,1695 Q4.2@3730.63,1695
  Bottom Layer w10: v2(1055,720) 1150,720 1175,695 1198.3,695 1203.04,699.74 v2@1204.04,700.74 ; 1214.78,692 1644.57,692 1741.31,788.74 SW2.1@1805.04,788.74 ; SW2.1@1790.04,788.74 SW2.1@1805.04,788.74 ; J7.6@2675.04,1258.74 2675.04,1136.74 2347.04,808.74 1825.04,808.74 SW2.1@1805.04,788.74
  Bottom Layer w15: v7(2958.79,1575) 2958.79,1580 2983,1580 3035,1632 v7@3230,1632
DUT_SCL: J16.2 J17.2 R12.2 R30.1 | length 1704.6
  Top Layer w10: J16.2@3075.04,2460 3085,2460 3170,2545 3820,2545 J17.2@3905,2460 ; R12.2@3135,1800 3165,1800 R30.1@3203.31,1800 ; R12.2@3150,1816 3150.5,1815.5 3157.5,1808.5 3165,1801 ; R30.1@3205,1798.31 R30.1@3205,1800 ; R30.1@3220,1800 3220,1810 R30.1@3220,1812.69 ; J17.2@3890,2460 J17.2@3905,2460 ; J17.2@3910.02,2465.02 J17.2@3915.04,2460 J17.2@3905,2460
  Bottom Layer w10: J16.2@3084.3,2450.74 3084.3,1896.7 v2(3165,1816)
DUT_SDA: J16.4 J17.4 R13.2 R29.1 | length 1034.3
  Top Layer w10: R13.2@3135,2010 3175,2010 R29.1@3199,2010 ; J16.4@3280.02,2455.02 3345,2520 3655.04,2520 J17.4@3715.04,2460
  Bottom Layer w10: v2@3175,2015 v2(3175,2020) 3175,2310 3280.02,2415.02 J16.4@3280.02,2455.02
FAIL: D4.2 U2.22 | length 476
  Top Layer w10: D4.2@3280.59,555 3360.14,555 3497.35,692.22 3497.35,819.59 3475.66,841.28 U2.22@3475.66,885.65
GND_POWER: C1.2 C3.2 C4.2 C5.2 C6.2 C7.1 C8.1 C9.2 C10.2 C11.2 C13.2 C14.1 C15.1 C16.2 C17.2 C18.1 CN1.17 CN1.41 CN1.69 CN1.107 J1.A1 J1.A12 J1.M1 J1.M2 J1.M3 J1.M4 J3.2 J4.5 J6.2 J7.5 J12.1 J12.2 J12.3 J12.4 J17.5 J18.3 Q3.3 Q4.3 R2.2 R3.2 R4.2 R5.1 R8.2 R20.2 R21.2 R22.1 R24.2 R25.2 R26.2 R27.1 R28.2 R43.1 R60.2 R62.1 R63.1 SW2.2 SW3.2 U1.2 U2.42 U3.3 U4.20 U5.31 U8.4 U9.4 | length 3377.1
  Top Layer w8: 3619.08,1099.79 3625.08,1105.79 3655.59,1105.79 3680.76,1105.79 3685.59,1100.96 3685.59,1058 3685.59,1050.5 3677.59,1050.5 3625.59,1050.5 3625.59,983.5 3690.59,983.5 3698.59,983.5 3698.59,977 3698.59,955.04 3641.57,898.02 ; v1@3619.59,1164 3625.12,1158.47 3729.12,1158.47 ; 3641.57,747.52 cw(c3653.59,759.54) 3636.59,759.54 ; 3641.59,898 ccw(c3653.61,885.98) 3636.61,885.98 3636.59,759.54 ; 3674.21,687.57 ccw(c3686.23,699.59) 3686.23,682.59 cw(c3686.23,699.59) 3674.19,687.59 3668.59,693.19 ; 3694.59,781.64 3688.59,787.64 3688.59,825 3688.59,871.5 3787.59,970.5 ccw(c3775.59,982.54) 3792.59,982.54 cw(c3775.59,982.54) 3787.61,970.52 ; 3792.59,983.5 3802.59,983.5 3865.59,983.5 3865.59,1050.5 3813.59,1050.5 3805.59,1050.5 3805.59,1059 3805.59,1116.5 3778.13,1116.5 3758.11,1136.52 3741.16,1153.47 ; 3636.59,759.54 ccw(c3653.59,759.54) 3641.59,747.5 3660.34,728.75 3663.59,725.5 3663.59,722 3663.59,705.23 ; 3663.59,705.23 ccw(c3680.59,705.23) 3668.59,693.19 ; 3663.59,705.23 ccw(c3680.59,705.23) 3668.57,693.21 ; 3729.12,1158.47 cw(c3729.12,1141.47) 3741.16,1153.47 ; 3729.12,1158.47 cw(c3729.12,1141.47) 3741.14,1153.49
  Top Layer w9: U5.31@1351.02,976.5 1390,976.5 1451.02,976.5
  Top Layer w10: U2.42@3416.6,1223.13 3416.6,1283.6 v4(3425,1292) 3429,1296 3441,1296 3461,1316
  Top Layer w12: 3455,1919.53 U9.4@3486.02,1919.53 ; U8.4@3471.02,2049.53 U8.4@3486.02,2049.53 3510,2049.53 3525.47,2049.53 3561.5,2013.5 R4.2@3565,2010 ; 3623.59,1083 C1.2@3655.59,1083 C1.2@3656.59,1083 ; 3656.59,1054 C1.2@3656.59,1083 ; C1.2@3656.59,1091 C1.2@3656.59,1083 ; 3683.59,1083 C1.2@3656.59,1083
  Top Layer w15: U4.20@918.43,1187.5 918.43,1295.74 918.43,1353.74 v1@918.43,1378.44 ; 920,1353.74 v1@920,1378.44 ; Q3.3@3645.29,1635.29 3676.24,1666.24 3753.7,1666.24 3777.54,1642.4 Q4.3@3777.54,1623.03
  Top Layer w20: R3.2@3051.04,1010 3051.04,1090 R2.2@3051.04,1090.09 ; C9.2@3477.04,1528 3477.04,1540.47 3477.04,1582 R21.2@3477.04,1620 ; R22.1@3543.59,461 3543.59,457 3543.59,395.74 3543.59,391.89 3545.39,390.09 3559.03,376.44 3590.08,345.4 ; R20.2@3639.04,1515 3639.04,1523 Q3.3@3639.04,1612.53
  Top Layer w22: 3670.59,621.9 3689.38,603.12 J1.A1@3763.84,603.12 J1.A1@3815.59,603.12 ; 3718.47,522.79 3718.47,580 J1.A1@3718.47,597.25
  Top Layer w25: C18.1@937,734 937,735 v1(937,760)
  Top Layer w30: R63.1@3212,1880 v3(3212,1920) R62.1@3212,1955 ; v1@3220,1855 R63.1@3220,1875
  Top Layer w40: J7.5@2675.04,1358.74 J4.5@2875.04,1358.74
  Top Layer w50: 3841.82,2125 U1.2@3905,2125 U1.2@3966.38,2125
  other v1: 2475.04,30.64 349.94,48.74 1115.04,50.64 1675.04,50.64 3647.59,51.9 2879.94,75 2026.04,160.64 2339.94,185 3205.59,191.9 2098.04,210.64 3596.59,231.9 1039.94,250.74 719.94,256.74 2083.04,270.64 3479.94,285 2699.94,293.74 1189.94,295 1475,300.64 2466,310.64 3322.59,316 3197.59,317 75.04,320.64 3579.94,323.74 2320,330.64 3755,350.64 2074.04,360.64 3384.04,380.64 3551.04,395.74 3755,450.64 2336.04,470.64 3339.94,518 2969.94,520 1969.94,524.74 1839.94,545.74 1319.94,565 1529.94,575 3715.59,580 2416.04,600.64 482.04,610.64 3275.04,610.64 2845.04,620 615,620.64 3339.94,662.74 4055.59,671.9 3653.59,722 3299.94,725.74 3125.04,751.9 2969.94,756 1359.94,782 1625,800.64 3289.94,816.74 3695.59,825 1415,830.64 2339.94,872.74 3712.59,874 685,875 2850,890.64 3628.59,891.9 2698.04,900.64 2999.94,930 2419.94,939.74 3345,940.64 3115,970.64 3802.59,976 3690.59,977 1390,983 1759.94,1000 1350,1020 3905.59,1031.9 2094.04,1050.64 3110,1050.64 3677.59,1058 3813.59,1059 3415,1060.64 2349.94,1102.74 524.04,1110.64 3290.04,1111.9 1499.94,1118.74 3155,1120.64 3765.59,1144 4040.59,1161.9 1211,1163 3624.59,1170 3525,1171 3169.94,1200 3249.94,1200 2579.94,1204.74 2099.94,1213.74 3575.04,1221.9 1375,1226.74 3265.04,1260 2932,1269.26 605.04,1300.64 3080,1300.64 519.94,1307.74 1720,1310.64 963,1312 75.04,1330.64 1101,1330.64 1280.04,1330.64 3924.59,1339 762.17,1350 2095.04,1350.64 827.17,1360 927.11,1378.74 1399.94,1403.74 4019.94,1405 1270.04,1410.64 2929.94,1415 2387,1470.64 1245,1510.64 3419.94,1515 997.11,1528.74 2110.04,1540.64 1682,1560.64 3225,1570.64 3055,1590.64 529.94,1603.74 3955,1616.26 1975.04,1650.64 3803.03,1680 3939.94,1730 3470,1745 3239.94,1755 3360,1755 635.04,1760.64 2465.04,1780.64 3435,1832.56 3225,1853 69.94,1853.74 2839.94,1890 3435,1890.64 1176.04,1940.64 3475,1950.64 3821.38,1950.94 1865.04,1990.64 2099.94,2003.74 3434.94,2035 3831.32,2040.94 3510,2060.64 3569.94,2065 2379.94,2068.74 679.94,2076.74 3055,2085 1709.94,2094.74 1889.94,2099.74 3719.94,2105 3109.94,2120 2605.04,2120.64 3265,2160.64 3535,2180.64 3649.94,2189.59 3055,2195 1765.04,2208.74 2099.94,2208.74 1130.04,2210.64 1629.94,2213.74 629.94,2218.74 3819.94,2225 3119.94,2230 69.94,2288.74 2839.94,2305 2690.04,2320.64 3359.94,2395 3675,2400.64 4049.94,2535 819.94,2558.74 325.04,2560.64 1445.04,2560.64 1950.04,2560.64 2839.94,2585
  other v3: 4040.04,181.9 3150,1400 3800,1511.26 3079.94,1515 3500.59,1582 3609.94,1600 4049.94,1795 3705,1850.64 3968.42,2041.59 3955.97,2201.69 4055,2290.64 3725,2299.69 2419.94,2538.74
  other v4: 3455.59,952 3008.11,1050 3430.59,1379 3585,1381.26 3506,1504
  other v8: 3750.59,1389
ICP/SWD_SCL: R40.1 U2.31 U9.2 | length 1093
  Top Layer w8: v2@3392,1168 3410,1150 3452,1150 3538.27,1063.73 U2.31@3575.5,1063.73
  Top Layer w12: U9.2@3486.02,1880.16 3514.84,1880.16 3525,1870 3525,1832 R40.1@3557,1800
  Bottom Layer w10: v2(3392,1175) 3373,1194 3373,1723 3455,1805 v6(3523.07,1805)
ICP/SWD_SDA: R41.1 R64.1 U2.33 | length 1167.1
  Top Layer w8: v2(3425,1175) 3456,1175 3527.9,1103.1 U2.33@3575.5,1103.1
  Top Layer w10: R64.1@3623,1965 3623,1955 3623,1890 3628,1885 3630,1883 v2(3630,1855)
  Bottom Layer w10: 3395,1505 3395,1495 ; v2@3423,1175 3423,1187 3395,1215 3395,1495 ; v2(3630,1855) 3630,1817 3589.47,1776.47 3461.47,1776.47 3395,1710 3395,1495
MLINK_RXD: CN1.3 D11.2 J5.2 J8.2 U4.5 U5.14 | length 3535.3
  Top Layer w8: CN1.3@675.04,358.74 675.04,383.74 625.04,433.74 625.04,485.04 805,665 ; U4.5@816.65,937.5 816.65,676.65 ; 818.35,676.65 830,665 ; U5.14@1177.8,913.5 1134.8,913.5 1120.04,898.74 1120.04,726.04 1078.5,684.5 1059,665 830,665 ; 805,665 816.65,676.65 ; 805,665 816.65,665 ; 816.65,665 830,665 ; 816.65,665 816.65,676.65
  Top Layer w10: J8.2@2675.04,1058.74 J5.2@2875.04,1058.74 ; J5.2@2875.04,1060 2935.04,1000 2935.04,825 D11.2@2935.04,810
  Bottom Layer w10: v2(1074,689) 1146,689 1173,662 1657,662 1703.74,708.74 2325.04,708.74 J8.2@2675.04,1058.74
